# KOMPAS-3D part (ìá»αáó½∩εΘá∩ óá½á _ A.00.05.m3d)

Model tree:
1. Эскиз:1
2. Операция выдавливания:2
     Расстояние 1 = 26; Расстояние 2 = 26; На расстояние 2 = 20
3. Отверстие:4
     Глубина выреза = 18; Диаметр отверстия = 10.3762; Угол конуса торца = 118; Угол 1 = -90; Расстояние 2 = -26
4. M12x1.5  (labels: A.00.05)
     Длина резьбы = 18; Шаг резьбы = 1.5; Номинальный диаметр резьбы = 12

Referenced files in C:\Program Files (x86)\ASCON\KOMPAS-3D V15\Sys\Thread\: cil1_24705-2004.xml
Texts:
  Сталь 40Х  ГОСТ 4543-71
